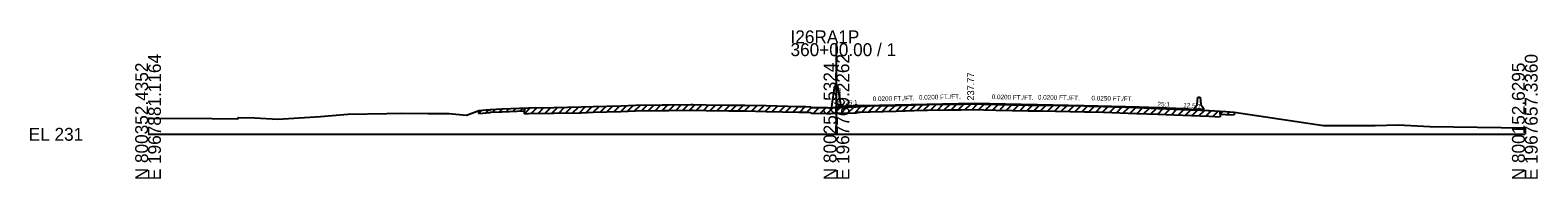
# Model space of a CAD drawing. Extents: x -26 to 304, y -10 to 7527.
# Drawn here: x -25.7 to 302.8, y 4990.3 to 5022.7 of the extents above; entities that cross this region are included whole.
import ezdxf

# ---------------------------------------------------------------- set-up
doc = ezdxf.new("R2010")
doc.units = 0
for name, color, linetype in [('Default', 7, 'Continuous'), ('RD_GPK_XS_Cell', 7, 'Continuous'), ('RD_XS_Base', 7, 'Continuous'), ('RD_XS_Box', 7, 'Continuous'), ('RD_XS_EarthShd', 7, 'Continuous'), ('RD_XS_ExGround', 7, 'Continuous'), ('RD_XS_ExPaveRet', 7, 'Continuous'), ('RD_XS_Misc_Line', 7, 'Continuous'), ('RD_XS_Pave', 7, 'Continuous'), ('RD_XS_PaveShd', 7, 'Continuous'), ('RD_XS_TX_Elev_EX', 7, 'Continuous'), ('RD_XS_TX_Elev_PR', 7, 'Continuous'), ('RD_XS_TX_Misc', 7, 'Continuous'), ('RD_XS_TX_MkPT', 7, 'Continuous'), ('RD_XS_TX_Profile', 7, 'Continuous'), ('RD_XS_TX_Station', 7, 'Continuous')]:
    doc.layers.add(name, color=color, linetype=linetype)

msp = doc.modelspace()

# ---------------------------------------------------------------- linework, layer by layer
at = {"layer": 'Default'}
for p, q in [((228.58, 5006.52), (228.75, 5008.1)), ((228.75, 5008.1), (229.25, 5008.1)), ((229.25, 5008.1), (229.42, 5006.52)), ((228, 5005.68), (228.58, 5006.52)), ((228, 5005.43), (228, 5005.68)), ((230, 5005.43), (228, 5005.43)), ((229.42, 5006.52), (230, 5005.68)), ((230, 5005.68), (230, 5005.43))]:
    msp.add_line(p, q, dxfattribs=at)
at = {"layer": 'RD_GPK_XS_Cell'}
for p, q in [((150, 5000), (150, 5019.82)), ((0, 5000), (150, 5000)), ((150, 5000), (300, 5000))]:
    msp.add_line(p, q, dxfattribs=at)
at = {"layer": 'RD_XS_Base'}
for p, q in [((150, 5005.83), (150, 5006.05)), ((226, 5005.37), (226, 5005.59))]:
    msp.add_line(p, q, dxfattribs=at)
at = {"layer": 'RD_XS_Box'}
msp.add_line((228, 5005.43), (231.95, 5005.12), dxfattribs=at)
at = {"layer": 'RD_XS_EarthShd'}
for p, q in [((149, 5006.07), (149.67, 5010.55)), ((150, 5010.55), (149.67, 5010.55)), ((150, 5010.55), (150.33, 5010.55)), ((151, 5006.07), (150.33, 5010.55)), ((226, 5005.59), (228, 5005.43))]:
    msp.add_line(p, q, dxfattribs=at)
at = {"layer": 'RD_XS_ExGround'}
msp.add_lwpolyline([(0, 5003.5), (0.68, 5003.5), (13.97, 5003.42), (19.55, 5003.35), (19.65, 5003.65), (23.23, 5003.6), (28.26, 5003.32), (37.61, 5003.88), (43.52, 5004.39), (52.02, 5004.5), (55.24, 5004.6), (60.93, 5004.55), (65.63, 5004.49), (67.09, 5004.35), (69.38, 5004.16), (71.71, 5005.05), (72.07, 5005.19), (73.65, 5005.29), (74.46, 5005.34), (74.65, 5005.42), (77.06, 5005.53), (82.93, 5005.77), (88.4, 5005.85), (94.36, 5005.95), (96.99, 5006.03), (99.98, 5006.13), (103.01, 5006.22), (106.23, 5006.33), (112.02, 5006.42), (112.33, 5006.42), (113.48, 5006.44), (118.25, 5006.51), (118.71, 5006.5), (121.61, 5006.43), (126.57, 5006.37), (130.02, 5006.33), (134.7, 5006.24), (141.81, 5006.07), (143.31, 5006.03), (144.37, 5005.99), (144.66, 5005.86), (147.76, 5005.8), (148.35, 5005.79), (148.75, 5005.8), (150, 5005.83), (151.01, 5005.85), (151.59, 5005.87), (154.32, 5005.95), (154.58, 5006.06), (155.19, 5006.08), (157.32, 5006.17), (162.99, 5006.3), (168.91, 5006.48), (169.82, 5006.5), (174.17, 5006.54), (177.14, 5006.57), (181.09, 5006.61), (182.15, 5006.56), (184.75, 5006.47), (191.81, 5006.37), (193.14, 5006.36), (194.59, 5006.33), (204.07, 5006.16), (205.01, 5006.13), (208.23, 5006.05), (215.38, 5005.8), (220.14, 5005.63), (223.55, 5005.47), (231.21, 5005.16), (234.82, 5004.96), (236.7, 5004.85), (238.62, 5004.56), (256.14, 5001.93), (267.36, 5001.89), (272.43, 5002.05), (279.27, 5001.7), (300, 5001.43)], dxfattribs=at)
at = {"layer": 'RD_XS_ExPaveRet'}
for p, q in [((72.07, 5004.56), (72.07, 5005.19)), ((72.07, 5004.56), (73.65, 5004.66)), ((73.65, 5004.66), (74.46, 5004.71)), ((74.46, 5004.71), (74.65, 5004.79)), ((74.65, 5004.79), (77.06, 5004.9)), ((77.06, 5004.9), (82, 5005.1)), ((82, 5004.48), (82, 5005.73)), ((82, 5005.73), (82, 5005.1)), ((82, 5004.48), (82.93, 5004.52)), ((82.93, 5004.52), (88.4, 5004.6)), ((88.4, 5004.6), (94.36, 5004.7)), ((94.36, 5004.7), (96.99, 5004.78)), ((96.99, 5004.78), (99.98, 5004.88)), ((99.98, 5004.88), (103.01, 5004.97)), ((103.01, 5004.97), (106.23, 5005.08)), ((106.23, 5005.08), (112.02, 5005.17)), ((112.02, 5005.17), (112.33, 5005.17)), ((112.33, 5005.17), (113.48, 5005.19)), ((113.48, 5005.19), (118.25, 5005.26)), ((118.25, 5005.26), (118.71, 5005.25)), ((118.71, 5005.25), (121.61, 5005.18)), ((121.61, 5005.18), (126.57, 5005.12)), ((126.57, 5005.12), (130.02, 5005.08)), ((130.02, 5005.08), (134.7, 5004.99)), ((134.7, 5004.99), (141.81, 5004.82)), ((141.81, 5004.82), (143.31, 5004.78)), ((143.31, 5004.78), (144.37, 5004.74)), ((144.37, 5004.74), (144.66, 5004.61)), ((144.66, 5004.61), (147.76, 5004.55)), ((147.76, 5004.55), (148.35, 5004.54)), ((148.35, 5004.54), (148.75, 5004.55)), ((148.75, 5004.55), (150, 5004.58)), ((150, 5004.58), (151.01, 5004.6)), ((151.01, 5004.6), (151.59, 5004.62)), ((151.59, 5004.62), (154.32, 5004.7)), ((154.32, 5004.7), (154.58, 5004.81)), ((154.58, 5004.81), (155.19, 5004.83)), ((155.19, 5004.83), (157.32, 5004.92)), ((157.32, 5004.92), (162.99, 5005.05)), ((162.99, 5005.05), (168.91, 5005.23)), ((168.91, 5005.23), (169.82, 5005.25)), ((169.82, 5005.25), (174.17, 5005.29)), ((174.17, 5005.29), (177.14, 5005.32)), ((177.14, 5005.32), (181.09, 5005.36)), ((181.09, 5005.36), (182.15, 5005.31)), ((182.15, 5005.31), (184.75, 5005.22)), ((184.75, 5005.22), (191.81, 5005.12)), ((191.81, 5005.12), (193.14, 5005.11)), ((193.14, 5005.11), (194.59, 5005.08)), ((194.59, 5005.08), (204.07, 5004.91)), ((204.07, 5004.91), (205.01, 5004.88)), ((205.01, 5004.88), (208.23, 5004.8)), ((208.23, 5004.8), (215.38, 5004.55)), ((215.38, 5004.55), (220.14, 5004.38)), ((220.14, 5004.38), (223.55, 5004.22)), ((223.55, 5004.22), (231.21, 5003.91)), ((231.21, 5003.91), (233.63, 5003.77)), ((233.63, 5005.02), (233.63, 5003.77)), ((233.63, 5004.4), (233.63, 5005.02)), ((233.63, 5004.4), (234.82, 5004.33)), ((234.82, 5004.33), (236.7, 5004.22)), ((236.7, 5004.85), (236.7, 5004.22))]:
    msp.add_line(p, q, dxfattribs=at)
at = {"layer": 'RD_XS_Misc_Line'}
for p, q in [((72.07, 5004.56), (72.73, 5005.23)), ((73.57, 5004.66), (74.23, 5005.32)), ((75.07, 5004.81), (75.72, 5005.47)), ((76.57, 5004.88), (77.22, 5005.53)), ((78.07, 5004.94), (78.72, 5005.6)), ((79.57, 5005), (80.22, 5005.66)), ((81.07, 5005.07), (81.72, 5005.72)), ((82, 5004.48), (83.29, 5005.77)), ((83.5, 5004.52), (84.77, 5005.8)), ((85, 5004.55), (86.27, 5005.82)), ((86.5, 5004.57), (87.77, 5005.84)), ((88, 5004.6), (89.27, 5005.87)), ((89.5, 5004.62), (90.77, 5005.89)), ((91, 5004.64), (92.27, 5005.91)), ((92.5, 5004.67), (93.77, 5005.94)), ((94, 5004.69), (95.28, 5005.98)), ((95.5, 5004.73), (96.79, 5006.02)), ((97, 5004.78), (98.29, 5006.07)), ((98.5, 5004.83), (99.79, 5006.12)), ((100, 5004.88), (101.29, 5006.17)), ((101.5, 5004.92), (102.79, 5006.21)), ((103, 5004.97), (104.3, 5006.27)), ((104.5, 5005.02), (105.8, 5006.32)), ((106, 5005.08), (107.27, 5006.35)), ((107.5, 5005.1), (108.77, 5006.37)), ((109, 5005.12), (110.27, 5006.39)), ((110.5, 5005.14), (111.77, 5006.41)), ((112, 5005.17), (113.27, 5006.44)), ((113.5, 5005.19), (114.77, 5006.46)), ((115, 5005.21), (116.27, 5006.48)), ((116.5, 5005.23), (117.77, 5006.5)), ((118, 5005.25), (119.23, 5006.48)), ((119.5, 5005.23), (120.72, 5006.45)), ((121, 5005.19), (122.23, 5006.42)), ((122.5, 5005.17), (123.74, 5006.4)), ((124, 5005.15), (125.24, 5006.39)), ((125.5, 5005.13), (126.74, 5006.37)), ((127, 5005.12), (128.24, 5006.35)), ((128.5, 5005.1), (129.74, 5006.34)), ((130, 5005.09), (131.22, 5006.31)), ((131.5, 5005.05), (132.72, 5006.28)), ((133, 5005.02), (134.22, 5006.25)), ((134.5, 5004.99), (135.72, 5006.21)), ((136, 5004.96), (137.22, 5006.18)), ((137.5, 5004.92), (138.72, 5006.14)), ((139, 5004.89), (140.22, 5006.11)), ((140.5, 5004.85), (141.72, 5006.07)), ((142, 5004.82), (143.21, 5006.03)), ((143.5, 5004.77), (144.61, 5005.88)), ((145, 5004.6), (146.23, 5005.83)), ((146.5, 5004.57), (147.73, 5005.8)), ((148, 5004.55), (149.26, 5005.81)), ((149.5, 5004.56), (150.78, 5005.84)), ((151, 5004.6), (152.29, 5005.89)), ((152.5, 5004.65), (153.79, 5005.94)), ((154, 5004.69), (155.4, 5006.09)), ((155.5, 5004.85), (156.8, 5006.15)), ((157, 5004.91), (158.28, 5006.19)), ((158.5, 5004.95), (159.78, 5006.23)), ((160, 5004.98), (161.28, 5006.26)), ((161.5, 5005.01), (162.78, 5006.29)), ((163, 5005.05), (164.29, 5006.34)), ((164.5, 5005.1), (165.79, 5006.39)), ((166, 5005.14), (167.29, 5006.43)), ((167.5, 5005.19), (168.79, 5006.48)), ((169, 5005.24), (170.27, 5006.5)), ((170.5, 5005.25), (171.76, 5006.52)), ((172, 5005.27), (173.26, 5006.53)), ((173.5, 5005.29), (174.76, 5006.55)), ((175, 5005.3), (176.26, 5006.56)), ((176.5, 5005.31), (177.76, 5006.58)), ((178, 5005.33), (179.26, 5006.59)), ((179.5, 5005.34), (180.76, 5006.6)), ((181, 5005.36), (182.2, 5006.56)), ((182.5, 5005.3), (183.71, 5006.51)), ((184, 5005.25), (185.22, 5006.47)), ((185.5, 5005.21), (186.73, 5006.45)), ((187, 5005.19), (188.23, 5006.42)), ((188.5, 5005.17), (189.73, 5006.4)), ((190, 5005.15), (191.23, 5006.38)), ((191.5, 5005.13), (192.74, 5006.36)), ((193, 5005.11), (194.23, 5006.34)), ((194.5, 5005.08), (195.73, 5006.31)), ((196, 5005.05), (197.23, 5006.28)), ((197.5, 5005.03), (198.73, 5006.25)), ((199, 5005), (200.23, 5006.23)), ((200.5, 5004.97), (201.73, 5006.2)), ((202, 5004.95), (203.23, 5006.17)), ((203.5, 5004.92), (204.72, 5006.14)), ((205, 5004.88), (206.22, 5006.1)), ((206.5, 5004.85), (207.72, 5006.07)), ((208, 5004.81), (209.21, 5006.02)), ((209.5, 5004.76), (210.71, 5005.96)), ((211, 5004.7), (212.21, 5005.91)), ((212.5, 5004.65), (213.71, 5005.86)), ((214, 5004.6), (215.21, 5005.81)), ((215.5, 5004.55), (216.71, 5005.75)), ((217, 5004.49), (218.21, 5005.7)), ((218.5, 5004.44), (219.71, 5005.65)), ((220, 5004.38), (221.2, 5005.58)), ((221.5, 5004.32), (222.7, 5005.51)), ((223, 5004.25), (224.2, 5005.45)), ((224.5, 5004.19), (225.7, 5005.39)), ((226, 5004.12), (227.2, 5005.32)), ((227.5, 5004.06), (228.7, 5005.26)), ((229, 5004), (230.2, 5005.2)), ((230.5, 5003.94), (231.69, 5005.13)), ((232, 5003.86), (233.18, 5005.05)), ((233.63, 5004.4), (234.22, 5004.99)), ((235.13, 5004.31), (235.72, 5004.9))]:
    msp.add_line(p, q, dxfattribs=at)
at = {"layer": 'RD_XS_Pave'}
for p, q in [((156, 5006.29), (180, 5006.77)), ((180, 5006.77), (204, 5006.29)), ((204, 5006.29), (216, 5005.99))]:
    msp.add_line(p, q, dxfattribs=at)
at = {"layer": 'RD_XS_PaveShd'}
for p, q in [((156, 5006.29), (150, 5006.05)), ((216, 5005.99), (226, 5005.59))]:
    msp.add_line(p, q, dxfattribs=at)
at = {"layer": 'RD_XS_TX_Elev_PR'}
for p, q in [((148.35, 5005.79), (148.75, 5005.8)), ((150, 5005.83), (151.01, 5005.85)), ((151.01, 5005.85), (151.59, 5005.87)), ((151.59, 5005.87), (154.32, 5005.95)), ((154.32, 5005.95), (154.58, 5006.06)), ((154.58, 5006.06), (155.19, 5006.08)), ((155.19, 5006.08), (157.32, 5006.17)), ((157.32, 5006.17), (162.99, 5006.3)), ((162.99, 5006.3), (168.91, 5006.48)), ((168.91, 5006.48), (169.82, 5006.5)), ((169.82, 5006.5), (174.17, 5006.54)), ((174.17, 5006.54), (177.14, 5006.57)), ((177.14, 5006.57), (181.09, 5006.61)), ((181.09, 5006.61), (182.15, 5006.56)), ((182.15, 5006.56), (184.75, 5006.47)), ((184.75, 5006.47), (191.81, 5006.37)), ((191.81, 5006.37), (193.14, 5006.36)), ((193.14, 5006.36), (194.59, 5006.33)), ((194.59, 5006.33), (204.07, 5006.16)), ((204.07, 5006.16), (205.01, 5006.13)), ((205.01, 5006.13), (208.23, 5006.05)), ((208.23, 5006.05), (215.38, 5005.8)), ((215.38, 5005.8), (220.14, 5005.63)), ((220.14, 5005.63), (223.55, 5005.47)), ((223.55, 5005.47), (226, 5005.37))]:
    msp.add_line(p, q, dxfattribs=at)

# ---------------------------------------------------------------- texts
at = {"layer": 'RD_GPK_XS_Cell'}
for s, p in [('I26RA1P', (140, 5019.82)), ('360+00.00 / 1', (140, 5017.02)), ('EL 231', (-26, 4998.6))]:
    msp.add_text(s, height=2.8, dxfattribs=at).set_placement(p)
for s, p in [('E 1967881.1164', (2.8, 4990)), ('E 1967769.2262', (152.8, 4990)), ('E 1967657.3360', (302.8, 4990)), ('N 800352.4352', (0, 4990)), ('N 800252.5324', (150, 4990)), ('N 800152.6295', (300, 4990))]:
    msp.add_text(s, height=2.8, rotation=90, dxfattribs=at).set_placement(p)
at = {"layer": 'RD_XS_TX_Elev_EX'}
msp.add_text('236.83', height=1, rotation=90, dxfattribs=at).set_placement((151, 5005.83))
at = {"layer": 'RD_XS_TX_Misc'}
msp.add_text('12.5:1', height=1, rotation=355.4261, dxfattribs=at).set_placement((225.54, 5005.88))
at = {"layer": 'RD_XS_TX_MkPT'}
for rotation, p in [(2.2906, (151.94, 5006.38)), (357.7094, (219.96, 5006.09))]:
    msp.add_text('25:1', height=1, rotation=rotation, dxfattribs=at).set_placement(p)
at = {"layer": 'RD_XS_TX_Profile'}
for s, rotation, p in [('0.0200 FT./FT.', 1.1458, (157.92, 5007.22)), ('0.0200 FT./FT.', 1.1458, (167.98, 5007.53)), ('0.0200 FT./FT.', 358.5679, (183.83, 5007.68)), ('0.0200 FT./FT.', 358.8542, (193.89, 5007.57)), ('0.0250 FT./FT.', 358.8542, (205.57, 5007.38))]:
    msp.add_text(s, height=1, rotation=rotation, dxfattribs=at).set_placement(p)
at = {"layer": 'RD_XS_TX_Station'}
msp.add_text(' 237.77', height=1.5, rotation=90, dxfattribs=at).set_placement((180, 5006.77))

doc.saveas('drawing.dxf')
